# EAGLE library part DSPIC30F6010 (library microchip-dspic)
dsPIC Motion Controller DSP
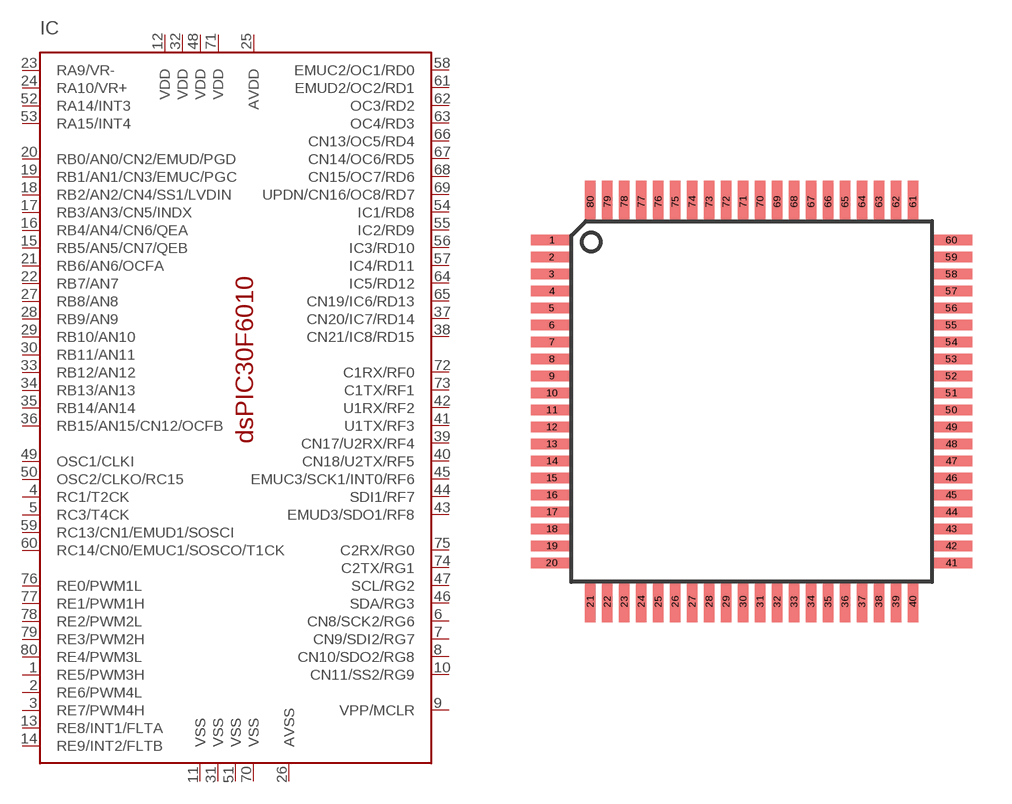
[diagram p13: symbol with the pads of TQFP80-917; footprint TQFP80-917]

Designator prefix IC

## DSPIC30F6010/PF  [TQFP80-917]
1  RE5/PWM3H
2  RE6/PWM4L
3  RE7/PWM4H
4  RC1/T2CK
5  RC3/T4CK
6  CN8/SCK2/RG6
7  CN9/SDI2/RG7
8  CN10/SDO2/RG8
9  VPP/MCLR  in
10  CN11/SS2/RG9
11  VSS  pwr
12  VDD  pwr
13  RE8/INT1/FLTA
14  RE9/INT2/FLTB
15  RB5/AN5/CN7/QEB
16  RB4/AN4/CN6/QEA
17  RB3/AN3/CN5/INDX
18  RB2/AN2/CN4/SS1/LVDIN
19  RB1/AN1/CN3/EMUC/PGC
20  RB0/AN0/CN2/EMUD/PGD
21  RB6/AN6/OCFA
22  RB7/AN7
23  RA9/VR-
24  RA10/VR+
25  AVDD  pwr
26  AVSS  pwr
27  RB8/AN8
28  RB9/AN9
29  RB10/AN10
30  RB11/AN11
31  VSS  pwr
32  VDD  pwr
33  RB12/AN12
34  RB13/AN13
35  RB14/AN14
36  RB15/AN15/CN12/OCFB
37  CN20/IC7/RD14
38  CN21/IC8/RD15
39  CN17/U2RX/RF4
40  CN18/U2TX/RF5
41  U1TX/RF3
42  U1RX/RF2
43  EMUD3/SDO1/RF8
44  SDI1/RF7
45  EMUC3/SCK1/INT0/RF6
46  SDA/RG3
47  SCL/RG2
48  VDD  pwr
49  OSC1/CLKI  in
50  OSC2/CLKO/RC15
51  VSS  pwr
52  RA14/INT3
53  RA15/INT4
54  IC1/RD8
55  IC2/RD9
56  IC3/RD10
57  IC4/RD11
58  EMUC2/OC1/RD0
59  RC13/CN1/EMUD1/SOSCI
60  RC14/CN0/EMUC1/SOSCO/T1CK
61  EMUD2/OC2/RD1
62  OC3/RD2
63  OC4/RD3
64  IC5/RD12
65  CN19/IC6/RD13
66  CN13/OC5/RD4
67  CN14/OC6/RD5
68  CN15/OC7/RD6
69  UPDN/CN16/OC8/RD7
70  VSS  pwr
71  VDD  pwr
72  C1RX/RF0
73  C1TX/RF1
74  C2TX/RG1
75  C2RX/RG0
76  RE0/PWM1L
77  RE1/PWM1H
78  RE2/PWM2L
79  RE3/PWM2H
80  RE4/PWM3L

## Footprint TQFP80-917 (pad centres in mm)
Thin Quad Flat Pack
smd 1.6 x 0.4: 1 -7.65,6.175; 2 -7.65,5.525; 3 -7.65,4.875; 4 -7.65,4.225; 5 -7.65,3.575; 6 -7.65,2.925; 7 -7.65,2.275; 8 -7.65,1.625; 9 -7.65,0.975; 10 -7.65,0.325; 11 -7.65,-0.325; 12 -7.65,-0.975; 13 -7.65,-1.625; 14 -7.65,-2.275; 15 -7.65,-2.925; 16 -7.65,-3.575; 17 -7.65,-4.225; 18 -7.65,-4.875; 19 -7.65,-5.525; 20 -7.65,-6.175; 41 7.65,-6.175; 42 7.65,-5.525; 43 7.65,-4.875; 44 7.65,-4.225; 45 7.65,-3.575; 46 7.65,-2.925; 47 7.65,-2.275; 48 7.65,-1.625; 49 7.65,-0.975; 50 7.65,-0.325; 51 7.65,0.325; 52 7.65,0.975; 53 7.65,1.625; 54 7.65,2.275; 55 7.65,2.925; 56 7.65,3.575; 57 7.65,4.225; 58 7.65,4.875; 59 7.65,5.525; 60 7.65,6.175
smd 0.4 x 1.6: 21 -6.175,-7.65; 22 -5.525,-7.65; 23 -4.875,-7.65; 24 -4.225,-7.65; 25 -3.575,-7.65; 26 -2.925,-7.65; 27 -2.275,-7.65; 28 -1.625,-7.65; 29 -0.975,-7.65; 30 -0.325,-7.65; 31 0.325,-7.65; 32 0.975,-7.65; 33 1.625,-7.65; 34 2.275,-7.65; 35 2.925,-7.65; 36 3.575,-7.65; 37 4.225,-7.65; 38 4.875,-7.65; 39 5.525,-7.65; 40 6.175,-7.65; 61 6.175,7.65; 62 5.525,7.65; 63 4.875,7.65; 64 4.225,7.65; 65 3.575,7.65; 66 2.925,7.65; 67 2.275,7.65; 68 1.625,7.65; 69 0.975,7.65; 70 0.325,7.65; 71 -0.325,7.65; 72 -0.975,7.65; 73 -1.625,7.65; 74 -2.275,7.65; 75 -2.925,7.65; 76 -3.575,7.65; 77 -4.225,7.65; 78 -4.875,7.65; 79 -5.525,7.65; 80 -6.175,7.65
